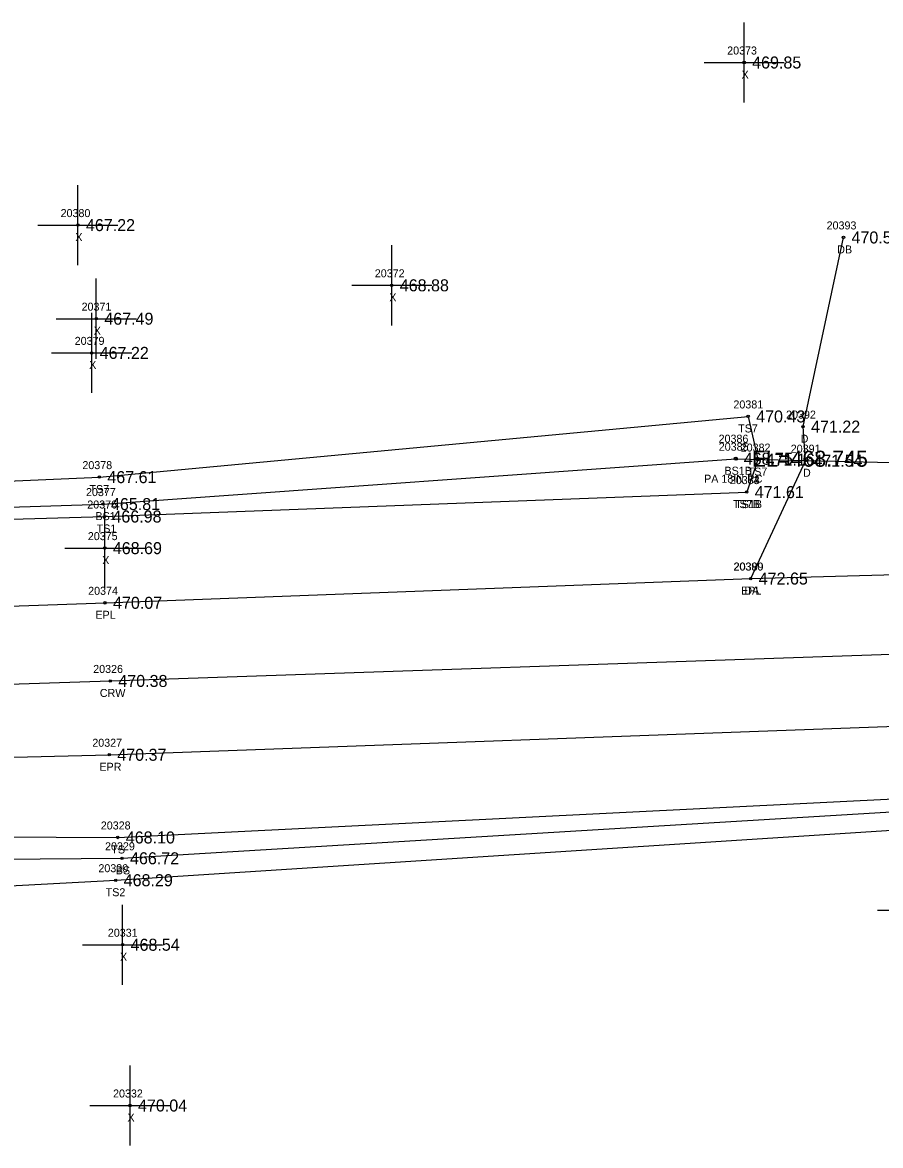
# Model space of a CAD drawing. Extents: x 1785066 to 1786589, y 770293 to 771312.
# Drawn here: x 1786267.8 to 1786374.9, y 770812.5 to 770952.8 of the extents above; entities that cross this region are included whole.
import ezdxf

# ---------------------------------------------------------------- set-up
doc = ezdxf.new("R2010")
doc.units = 0
for name, color, linetype in [('Default', 7, 'Continuous'), ('RD_DTM_BkLn1', 7, 'Continuous'), ('RD_DTM_BkLn2', 7, 'Continuous'), ('RD_DTM_BkLn_txCode', 7, 'Continuous'), ('RD_EX_DR_Pipe_txCode', 7, 'Continuous'), ('RD_EX_Driveway', 7, 'Continuous'), ('RD_EX_Driveway_txCode', 7, 'Continuous'), ('RD_EX_Misc', 7, 'Continuous'), ('RD_EX_Misc_txCode', 7, 'Continuous'), ('RD_EX_Road', 7, 'Continuous'), ('RD_EX_Road_txCode', 7, 'Continuous'), ('RD_EX_TX_Driveway_ELEV', 7, 'Continuous'), ('RD_EX_TX_Misc_ELEV', 7, 'Continuous'), ('RD_EX_TX_Road_ELEV', 7, 'Continuous'), ('RD_HC_Survey_ELEV', 7, 'Continuous'), ('RD_HC_Survey_txCode', 7, 'Continuous'), ('RD_SMD_Locator', 7, 'Continuous'), ('RD_TX_Pipe_ElevEX', 7, 'Continuous')]:
    doc.layers.add(name, color=color, linetype=linetype)

msp = doc.modelspace()

# ---------------------------------------------------------------- linework, layer by layer
at = {"layer": 'Default'}
msp.add_line((1786356.85, 770898.28), (1786381.45, 770897.7), dxfattribs=at)
at = {"layer": 'RD_DTM_BkLn1'}
msp.add_lwpolyline([(1785825, 770854.98), (1785879.1, 770857.22), (1785979.05, 770860.47), (1786078.95, 770863.87), (1786178.85, 770867.23), (1786278.74, 770870.52), (1786378.69, 770873.93), (1786478.55, 770877.83), (1786578.48, 770880.72)], dxfattribs=at)
at = {"layer": 'RD_DTM_BkLn2'}
for points in [[(1786077.7, 770886.77), (1786178.56, 770891.67), (1786277.37, 770895.98), (1786358.4, 770903.56), (1786359.59, 770898.17), (1786358.22, 770894.11)], [(1785823.92, 770890.03), (1785878.49, 770883.8), (1785927.98, 770885.02), (1785976.75, 770881.71), (1786078.01, 770885.31), (1786179.02, 770889.42), (1786277.82, 770892.61), (1786356.85, 770898.28)], [(1785823.56, 770878.59), (1785827.04, 770881.87), (1785879.17, 770873.62), (1785928.77, 770880.68), (1785976.07, 770878.36), (1786078.31, 770882.72), (1786179.21, 770888.23), (1786278, 770891.06), (1786358.22, 770894.11)], [(1786246.96, 770847.38), (1786248.77, 770851.12), (1786279.67, 770850.97), (1786379.11, 770855.94), (1786479.26, 770860.11), (1786579.22, 770863.72)], [(1786249.47, 770848.15), (1786280.2, 770848.37), (1786379.05, 770854.35), (1786479.51, 770858.4), (1786579.5, 770861.84)], [(1786246.96, 770847.38), (1786249.88, 770844.07), (1786279.41, 770845.63), (1786378.93, 770852.05), (1786480.11, 770854.27), (1786579.39, 770853.78)]]:
    msp.add_lwpolyline(points, dxfattribs=at)
at = {"layer": 'RD_EX_Driveway'}
msp.add_lwpolyline([(1786358.72, 770883.31), (1786365.55, 770898.03), (1786365.26, 770902.29), (1786370.31, 770925.92)], dxfattribs=at)
at = {"layer": 'RD_EX_Misc'}
for p, q in [((1786357.9, 770942.77), (1786357.9, 770952.77)), ((1786352.9, 770947.77), (1786362.9, 770947.77)), ((1786274.69, 770922.46), (1786274.69, 770932.46)), ((1786269.69, 770927.46), (1786279.69, 770927.46)), ((1786313.89, 770914.94), (1786313.89, 770924.94)), ((1786276.99, 770910.77), (1786276.99, 770920.77)), ((1786308.89, 770919.94), (1786318.89, 770919.94)), ((1786271.99, 770915.77), (1786281.99, 770915.77)), ((1786276.41, 770906.5), (1786276.41, 770916.5)), ((1786271.41, 770911.5), (1786281.41, 770911.5)), ((1786278.05, 770882.11), (1786278.05, 770892.11)), ((1786273.05, 770887.11), (1786283.05, 770887.11)), ((1786280.27, 770832.57), (1786280.27, 770842.57)), ((1786374.57, 770841.87), (1786384.57, 770841.87)), ((1786275.27, 770837.57), (1786285.27, 770837.57)), ((1786281.2, 770812.49), (1786281.2, 770822.49)), ((1786276.2, 770817.49), (1786286.2, 770817.49))]:
    msp.add_line(p, q, dxfattribs=at)
at = {"layer": 'RD_EX_Road'}
for points in [[(1785824.57, 770864.86), (1785879.1, 770866.73), (1785977.08, 770869.67), (1786078.78, 770873.52), (1786179.09, 770876.83), (1786278.08, 770880.28), (1786358.72, 770883.31), (1786381.38, 770883.94), (1786478.25, 770886.75), (1786578.04, 770889.63)], [(1785825.31, 770845.6), (1785879.29, 770848.18), (1785979.17, 770851.29), (1786079.29, 770854.66), (1786178.79, 770858.1), (1786233.56, 770860.16), (1786246.2, 770860.52), (1786278.61, 770861.3), (1786379.15, 770864.94), (1786479.01, 770868.57), (1786578.78, 770871.53)]]:
    msp.add_lwpolyline(points, dxfattribs=at)
at = {"layer": 'RD_SMD_Locator'}
for centre, radius in [((1786357.9, 770947.77), 0.15), ((1786274.69, 770927.46), 0.15), ((1786370.31, 770925.92), 0.15), ((1786313.89, 770919.94), 0.15), ((1786276.99, 770915.77), 0.15), ((1786276.41, 770911.5), 0.15), ((1786358.4, 770903.56), 0.15), ((1786365.26, 770902.29), 0.15), ((1786356.85, 770898.28), 0.2), ((1786356.85, 770898.28), 0.15), ((1786359.59, 770898.17), 0.15), ((1786365.55, 770898.03), 0.15), ((1786277.37, 770895.98), 0.15), ((1786358.22, 770894.11), 0.15), ((1786358.22, 770894.11), 0.15), ((1786277.82, 770892.61), 0.15), ((1786278, 770891.06), 0.15), ((1786278.05, 770887.11), 0.15), ((1786358.72, 770883.31), 0.15), ((1786358.72, 770883.31), 0.15), ((1786278.08, 770880.28), 0.15), ((1786278.74, 770870.52), 0.15), ((1786278.61, 770861.3), 0.15), ((1786279.67, 770850.97), 0.15), ((1786280.2, 770848.37), 0.15), ((1786279.41, 770845.63), 0.15), ((1786280.27, 770837.57), 0.15), ((1786281.2, 770817.49), 0.15)]:
    msp.add_circle(centre, radius, dxfattribs=at)

# ---------------------------------------------------------------- texts
at = {"layer": 'RD_DTM_BkLn_txCode'}
for s, p in [('20381', (1786356.56, 770904.56)), ('TS7', (1786357.15, 770901.56)), ('20385', (1786354.73, 770899.28)), ('20382', (1786357.47, 770899.17)), ('20378', (1786275.25, 770896.98)), ('BS1B', (1786355.44, 770896.28)), ('TS7', (1786358.34, 770896.17)), ('20383', (1786356.11, 770895.11)), ('20384', (1786356.11, 770895.11)), ('20377', (1786275.7, 770893.61)), ('TS7', (1786276.13, 770893.98)), ('20376', (1786275.86, 770892.06)), ('TS7B', (1786356.51, 770892.11)), ('TS1B', (1786356.79, 770892.11)), ('BS1', (1786276.88, 770890.61)), ('TS1', (1786277.04, 770889.06)), ('20328', (1786277.55, 770851.97)), ('20329', (1786278.08, 770849.37)), ('TS', (1786278.87, 770848.97)), ('20330', (1786277.25, 770846.63)), ('BS', (1786279.42, 770846.37)), ('TS2', (1786278.16, 770843.63))]:
    msp.add_text(s, height=1, dxfattribs=at).set_placement(p)
at = {"layer": 'RD_EX_DR_Pipe_txCode'}
for s, p in [('20386', (1786354.71, 770900.28)), ('PA 18IN RC', (1786352.9, 770895.28))]:
    msp.add_text(s, height=1, dxfattribs=at).set_placement(p)
at = {"layer": 'RD_EX_Driveway_txCode'}
for s, p in [('20393', (1786368.2, 770926.92)), ('DB', (1786369.53, 770923.92)), ('20392', (1786363.14, 770903.29)), ('D', (1786364.96, 770900.29)), ('20391', (1786363.72, 770899.03)), ('D', (1786365.25, 770896.03)), ('20390', (1786356.56, 770884.31)), ('DA', (1786357.92, 770881.31))]:
    msp.add_text(s, height=1, dxfattribs=at).set_placement(p)
at = {"layer": 'RD_EX_Misc_txCode'}
for s, p in [('20373', (1786355.78, 770948.77)), ('X', (1786357.58, 770945.77)), ('20380', (1786272.53, 770928.46)), ('X', (1786274.37, 770925.46)), ('20372', (1786311.77, 770920.94)), ('X', (1786313.58, 770917.94)), ('20371', (1786275.15, 770916.77)), ('X', (1786276.67, 770913.77)), ('20379', (1786274.29, 770912.5)), ('X', (1786276.1, 770909.5)), ('20375', (1786275.93, 770888.11)), ('X', (1786277.73, 770885.11)), ('20331', (1786278.43, 770838.57)), ('X', (1786279.95, 770835.57)), ('20332', (1786279.08, 770818.49)), ('X', (1786280.88, 770815.49))]:
    msp.add_text(s, height=1, dxfattribs=at).set_placement(p)
at = {"layer": 'RD_EX_Road_txCode'}
for s, p in [('20389', (1786356.6, 770884.31)), ('20374', (1786275.97, 770881.28)), ('EPL', (1786357.51, 770881.31)), ('EPL', (1786276.88, 770878.28)), ('20327', (1786276.49, 770862.3)), ('EPR', (1786277.38, 770859.3))]:
    msp.add_text(s, height=1, dxfattribs=at).set_placement(p)
at = {"layer": 'RD_EX_TX_Driveway_ELEV'}
for s, p in [('470.57', (1786371.31, 770925.17)), ('471.22', (1786366.26, 770901.54)), ('471.54', (1786366.55, 770897.28)), ('472.65', (1786359.72, 770882.56))]:
    msp.add_text(s, height=1.5, dxfattribs=at).set_placement(p)
at = {"layer": 'RD_EX_TX_Misc_ELEV'}
for s, p in [('469.85', (1786358.9, 770947.02)), ('467.22', (1786275.69, 770926.71)), ('468.88', (1786314.89, 770919.19)), ('467.49', (1786277.99, 770915.02)), ('467.22', (1786277.41, 770910.75)), ('470.43', (1786359.4, 770902.81)), ('468.75', (1786357.85, 770897.53)), ('471.16', (1786360.59, 770897.42)), ('467.61', (1786278.37, 770895.23)), ('471.61', (1786359.22, 770893.36)), ('471.61', (1786359.22, 770893.36)), ('465.81', (1786278.82, 770891.86)), ('466.98', (1786279, 770890.31)), ('468.69', (1786279.05, 770886.36)), ('468.10', (1786280.67, 770850.22)), ('466.72', (1786281.2, 770847.62)), ('468.29', (1786280.41, 770844.88)), ('468.54', (1786281.27, 770836.82)), ('470.04', (1786282.2, 770816.74))]:
    msp.add_text(s, height=1.5, dxfattribs=at).set_placement(p)
at = {"layer": 'RD_EX_TX_Road_ELEV'}
for s, p in [('472.65', (1786359.72, 770882.56)), ('470.07', (1786279.08, 770879.53)), ('470.37', (1786279.61, 770860.55))]:
    msp.add_text(s, height=1.5, dxfattribs=at).set_placement(p)
at = {"layer": 'RD_HC_Survey_ELEV'}
msp.add_text('470.38', height=1.5, dxfattribs=at).set_placement((1786279.74, 770869.77))
at = {"layer": 'RD_HC_Survey_txCode'}
for s, p in [('20326', (1786276.6, 770871.52)), ('CRW', (1786277.43, 770868.52))]:
    msp.add_text(s, height=1, dxfattribs=at).set_placement(p)
at = {"layer": 'RD_TX_Pipe_ElevEX'}
msp.add_text('EL=468.745', height=2, dxfattribs=at).set_placement((1786358.85, 770897.28))

doc.saveas('drawing.dxf')
